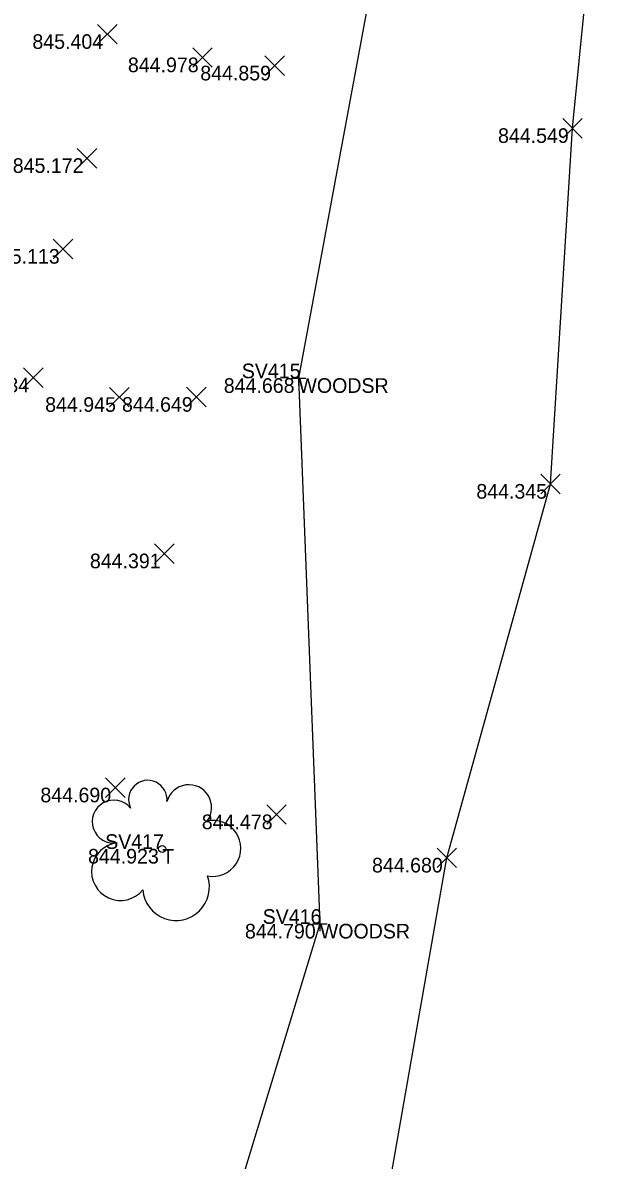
# Model space of a CAD drawing. Extents: x 2228183 to 2230895, y 679226 to 682223.
# Drawn here: x 2228383.3 to 2228423.2, y 680675.1 to 680752.8 of the extents above; entities that cross this region are included whole.
import ezdxf

# ---------------------------------------------------------------- set-up
doc = ezdxf.new("R2010")
doc.units = 0
for name, color, linetype in [('SC_Scratch1', 7, 'Continuous'), ('SV_P_Control_Cells_Set', 7, 'Continuous'), ('SV_X_Random_Point', 7, 'Continuous'), ('SV_X_Shot_Marker', 7, 'Continuous'), ('SV_X_Terrain_Boundary', 7, 'Continuous'), ('SV_X_Text_Comment', 7, 'Continuous'), ('VG_X_Cells', 7, 'Continuous'), ('VG_X_Tree_Line_Rt', 7, 'Continuous')]:
    doc.layers.add(name, color=color, linetype=linetype)

msp = doc.modelspace()

# ---------------------------------------------------------------- linework, layer by layer
at = {"layer": 'SV_X_Random_Point'}
for p, q in [((2228388.418, 680751.316), (2228389.752, 680752.651)), ((2228388.418, 680752.651), (2228389.752, 680751.316)), ((2228394.923, 680749.723), (2228396.257, 680751.058)), ((2228394.923, 680751.058), (2228396.257, 680749.723)), ((2228399.852, 680749.162), (2228401.186, 680750.497)), ((2228399.852, 680750.497), (2228401.186, 680749.162)), ((2228420.199, 680744.891), (2228421.533, 680746.226)), ((2228420.199, 680746.226), (2228421.533, 680744.891)), ((2228387.027, 680742.844), (2228388.361, 680744.179)), ((2228387.027, 680744.179), (2228388.361, 680742.844)), ((2228385.392, 680736.642), (2228386.726, 680737.977)), ((2228385.392, 680737.977), (2228386.726, 680736.642)), ((2228383.36, 680727.849), (2228384.694, 680729.184)), ((2228383.36, 680729.184), (2228384.694, 680727.849)), ((2228389.238, 680726.52), (2228390.572, 680727.855)), ((2228389.238, 680727.855), (2228390.572, 680726.52)), ((2228394.502, 680726.527), (2228395.836, 680727.862)), ((2228394.502, 680727.862), (2228395.836, 680726.527)), ((2228418.702, 680720.588), (2228420.036, 680721.923)), ((2228418.702, 680721.923), (2228420.036, 680720.588)), ((2228392.308, 680715.834), (2228393.642, 680717.169)), ((2228392.308, 680717.169), (2228393.642, 680715.834)), ((2228388.957, 680699.843), (2228390.291, 680701.178)), ((2228388.957, 680701.178), (2228390.291, 680699.843)), ((2228399.972, 680698.008), (2228401.306, 680699.343)), ((2228399.972, 680699.343), (2228401.306, 680698.008)), ((2228411.618, 680695.051), (2228412.952, 680696.386)), ((2228411.618, 680696.386), (2228412.952, 680695.051))]:
    msp.add_line(p, q, dxfattribs=at)
at = {"layer": 'SV_X_Shot_Marker'}
for p, q in [((2228401.642, 680728.483), (2228402.642, 680728.483)), ((2228402.142, 680728.983), (2228402.142, 680727.983)), ((2228402.142, 680728.483), (2228402.142, 680728.483)), ((2228403.602, 680691.708), (2228403.602, 680690.708)), ((2228403.102, 680691.208), (2228404.102, 680691.208)), ((2228403.602, 680691.208), (2228403.602, 680691.208))]:
    msp.add_line(p, q, dxfattribs=at)
at = {"layer": 'SV_X_Terrain_Boundary'}
msp.add_lwpolyline([(2228407.804, 680670.096), (2228412.285, 680695.718), (2228419.369, 680721.255), (2228420.866, 680745.558), (2228423.177, 680768.701)], dxfattribs=at)
at = {"layer": 'VG_X_Cells'}
msp.add_circle((2228392.831, 680696.328), 0.24, dxfattribs=at)
for centre, radius, start, end in [((2228391.847, 680699.696), 1.317, 354.0047, 205.97412), ((2228394.657, 680699.157), 1.553, 323.82996, 165.0376), ((2228389.522, 680698.192), 1.471, 39.06254, 279.54124), ((2228396.291, 680696.364), 1.915, 259.14531, 101.45961), ((2228389.978, 680694.779), 1.974, 96.17219, 320.57371), ((2228393.777, 680693.723), 2.284, 184.94757, 19.45715)]:
    msp.add_arc(centre, radius, start, end, dxfattribs=at)
at = {"layer": 'VG_X_Tree_Line_Rt'}
msp.add_lwpolyline([(2228410.452, 680773.345), (2228402.142, 680728.483), (2228403.602, 680691.208), (2228374.606, 680596.133), (2228370.969, 680582.119), (2228367.614, 680567.008), (2228346.3, 680486.661), (2228340.655, 680455.186), (2228334.048, 680383.235)], dxfattribs=at)

# ---------------------------------------------------------------- texts
at = {"layer": 'SC_Scratch1'}
for s, p in [('845.404', (2228383.963, 680750.983)), ('844.978', (2228390.49, 680749.39)), ('844.859', (2228395.435, 680748.829)), ('844.549', (2228415.782, 680744.558)), ('845.172', (2228382.621, 680742.511)), ('845.113', (2228380.995, 680736.309)), ('845.234', (2228378.905, 680727.516)), ('844.668', (2228397.042, 680727.483)), ('844.945', (2228384.835, 680726.187)), ('844.649', (2228390.085, 680726.194)), ('844.345', (2228414.299, 680720.255)), ('844.391', (2228387.893, 680715.501)), ('844.690', (2228384.51, 680699.51)), ('844.478', (2228395.539, 680697.675)), ('844.923', (2228387.767, 680695.328)), ('844.680', (2228407.171, 680694.718)), ('844.790', (2228398.488, 680690.208))]:
    msp.add_text(s, height=1, dxfattribs=at).set_placement(p)
at = {"layer": 'SV_P_Control_Cells_Set'}
for s, p in [('SV415', (2228398.272, 680728.483)), ('SV417', (2228388.935, 680696.328)), ('SV416', (2228399.698, 680691.208))]:
    msp.add_text(s, height=1, dxfattribs=at).set_placement(p)
at = {"layer": 'SV_X_Text_Comment'}
for s, p in [('WOODSR', (2228402.142, 680727.483)), ('T', (2228392.831, 680695.328)), ('WOODSR', (2228403.602, 680690.208))]:
    msp.add_text(s, height=1, dxfattribs=at).set_placement(p)

doc.saveas('drawing.dxf')
